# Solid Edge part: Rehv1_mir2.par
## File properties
Author: KULL
Template: Iso Metric Part.par
Last saved by: KULL
Revision: 2
Application: Solid Edge
Accuracy: 0,990
Username: KULL
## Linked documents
Rehv1.par
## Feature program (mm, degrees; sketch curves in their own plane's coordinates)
part copy "CopiedPart_1"
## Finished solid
Body 1: solid body, 650 faces, 1688 edges, 1040 vertices.
  Faces by surface: spline 520, torus 62, cylinder 54, cone 8, plane 6
  Edges by curve: intersection 1040, line 390, curve on surface 130, circle 128
Bounding box of the edges (mm; curved faces can reach further): 42.451 x 100.967 x 100.966, from (-41.2257, -50.4835, -50.483) to (1.2257, 50.4835, 50.483).
Cylindrical faces by radius (mm): R49.482 x1, R50.082 x52, R50.482 x1
Conical faces (half-angle, radius in mm at the cone's reference point): 14.1898 deg R43.1591 x1, 14.1898 deg R43.6493 x1, 14.1898 deg R44.4434 x1, 14.1898 deg R44.864 x1, 75.8102 deg R41.5194 x1, 75.8102 deg R41.7645 x1, 75.8102 deg R43.6493 x1, 75.8102 deg R44.864 x1
Toroidal faces (ring radius, tube radius in mm): R41.9116 r0.6 x2, R41.9116 r1.6 x2, R43.4159 r0.2 x2, R47.1178 r2.3642 x2, R47.1178 r2.9642 x52, R47.1178 r3.3642 x2
Planar faces by outward normal: +x 3, -x 3
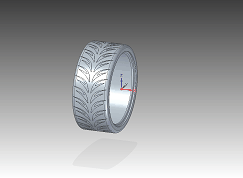
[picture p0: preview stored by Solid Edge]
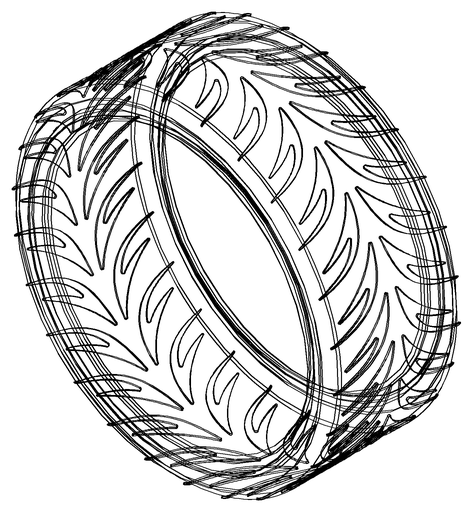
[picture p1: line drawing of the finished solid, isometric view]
